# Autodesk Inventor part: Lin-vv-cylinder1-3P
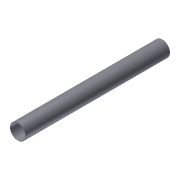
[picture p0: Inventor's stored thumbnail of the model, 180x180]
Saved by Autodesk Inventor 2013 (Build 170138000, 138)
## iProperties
Created: 2012-05
Part Number: Lin-vv-cylinder1-3P
Material: Steel
Description: VACUUM VESSEL CYLINDER
Document SubType Name: Modeling
Designer: Henneborn
Manufacturer: Standard
Standards Organization: Custom
Mass: 2.00027e+06 g
Surface Area: 535608 cm^2
Volume: 254811 cm^3
Density: 7.85 g/cm^3
Rohmasse: 38" O.D. x 0,375 WALL Tube
Author: vm
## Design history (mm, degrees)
sketch "Sketch1"
  geometry: C1 r 482.6 at (0, 0); C2 r 473.075 at (0, 0); 1 further point
  constraints: 2 centre point, 1 coincident
  dimensions: "d0" = 965.2 diameter of C1; "d1" = 9.525 radial gap between concentric circles of C1 C2
extrude "Extrusion1" new body sketch "Sketch1" stored distance "d2" = 8991.6; taper "d3" = 0 deg
body "Solid1"
